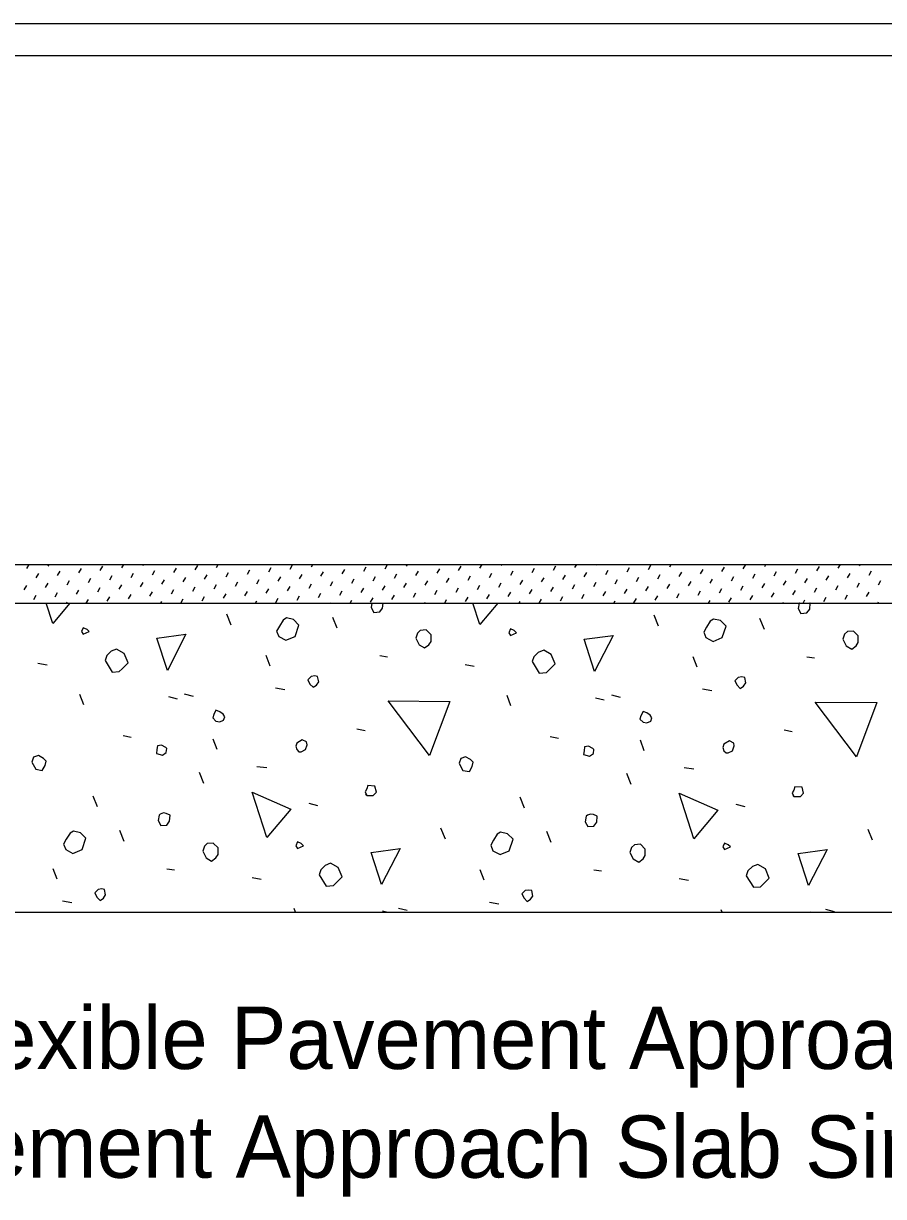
# Model space of a CAD drawing. Extents: x 130649.2 to 130733.9, y 88659.3 to 88705.5.
# Drawn here: x 130675.883 to 130678.667, y 88685.836 to 88689.631 of the extents above; entities that cross this region are included whole.
import ezdxf

# ---------------------------------------------------------------- set-up
doc = ezdxf.new("R2010")
doc.units = 0
for name, color, linetype in [('AdhocPoint_dp', 7, 'Continuous'), ('PlotBorder_dp', 7, 'Continuous'), ('TextMisc', 7, 'Continuous')]:
    doc.layers.add(name, color=color, linetype=linetype)

msp = doc.modelspace()

# ---------------------------------------------------------------- linework, layer by layer
at = {"layer": 'AdhocPoint_dp'}
for p, q in [((130673.2282, 88689.6313), (130686.5589, 88689.6313)), ((130673.2282, 88689.5271), (130686.5589, 88689.5271)), ((130673.2282, 88687.8812), (130689.0593, 88687.8812)), ((130673.2282, 88687.7562), (130689.0593, 88687.7562)), ((130673.2282, 88686.7562), (130689.0593, 88686.7562))]:
    msp.add_line(p, q, dxfattribs=at)
at = {"layer": 'TextMisc'}
for p, q in [((130675.8941, 88687.8679), (130675.9019, 88687.8812)), ((130675.9633, 88687.876), (130675.9663, 88687.8812)), ((130675.9938, 88687.8454), (130676.0019, 88687.8594)), ((130676.063, 88687.8535), (130676.0711, 88687.8675)), ((130676.1322, 88687.8616), (130676.1403, 88687.8756)), ((130676.2013, 88687.8697), (130676.208, 88687.8812)), ((130676.2705, 88687.8778), (130676.2724, 88687.8812)), ((130676.301, 88687.8473), (130676.3091, 88687.8613)), ((130676.3702, 88687.8554), (130676.3783, 88687.8694)), ((130676.4393, 88687.8635), (130676.4474, 88687.8775)), ((130676.5085, 88687.8716), (130676.5141, 88687.8812)), ((130676.5777, 88687.8797), (130676.5785, 88687.8812)), ((130676.6082, 88687.8492), (130676.6163, 88687.8632)), ((130676.6774, 88687.8573), (130676.6855, 88687.8713)), ((130676.7465, 88687.8654), (130676.7546, 88687.8794)), ((130676.8157, 88687.8735), (130676.8202, 88687.8812)), ((130676.8462, 88687.843), (130676.8543, 88687.857)), ((130676.9154, 88687.8511), (130676.9235, 88687.8651)), ((130676.9846, 88687.8592), (130676.9927, 88687.8732)), ((130677.0537, 88687.8673), (130677.0618, 88687.8812)), ((130677.1229, 88687.8754), (130677.1263, 88687.8812)), ((130677.1534, 88687.8449), (130677.1615, 88687.8588)), ((130677.2226, 88687.853), (130677.2307, 88687.8669)), ((130677.2917, 88687.8611), (130677.2998, 88687.875)), ((130677.3609, 88687.8692), (130677.3679, 88687.8812)), ((130677.4301, 88687.8773), (130677.4324, 88687.8812)), ((130677.4606, 88687.8467), (130677.4687, 88687.8607)), ((130677.5298, 88687.8548), (130677.5379, 88687.8688)), ((130677.5989, 88687.8629), (130677.607, 88687.8769)), ((130677.6681, 88687.871), (130677.674, 88687.8812)), ((130677.7373, 88687.8791), (130677.7385, 88687.8812)), ((130677.7678, 88687.8486), (130677.7759, 88687.8626)), ((130677.837, 88687.8567), (130677.8451, 88687.8707)), ((130677.9061, 88687.8648), (130677.9142, 88687.8788)), ((130677.9753, 88687.8729), (130677.9801, 88687.8812)), ((130678.0058, 88687.8424), (130678.0139, 88687.8564)), ((130678.0444, 88687.881), (130678.0446, 88687.8812)), ((130678.075, 88687.8505), (130678.0831, 88687.8645)), ((130678.1441, 88687.8586), (130678.1522, 88687.8726)), ((130678.2133, 88687.8667), (130678.2214, 88687.8807)), ((130678.2825, 88687.8748), (130678.2862, 88687.8812)), ((130678.313, 88687.8443), (130678.3211, 88687.8583)), ((130678.3822, 88687.8524), (130678.3903, 88687.8664)), ((130678.4513, 88687.8605), (130678.4594, 88687.8745)), ((130678.5205, 88687.8686), (130678.5278, 88687.8812)), ((130678.5897, 88687.8767), (130678.5923, 88687.8812)), ((130678.6202, 88687.8461), (130678.6283, 88687.8601)), ((130675.9247, 88687.8373), (130675.9328, 88687.8513)), ((130675.9552, 88687.8068), (130675.9633, 88687.8208)), ((130676.0244, 88687.8149), (130676.0325, 88687.8289)), ((130676.0935, 88687.823), (130676.1016, 88687.837)), ((130676.1627, 88687.8311), (130676.1708, 88687.8451)), ((130676.2319, 88687.8392), (130676.24, 88687.8532)), ((130676.2624, 88687.8087), (130676.2705, 88687.8227)), ((130676.3316, 88687.8168), (130676.3397, 88687.8308)), ((130676.4007, 88687.8249), (130676.4088, 88687.8389)), ((130676.4699, 88687.833), (130676.478, 88687.847)), ((130676.539, 88687.8411), (130676.5471, 88687.8551)), ((130676.5696, 88687.8106), (130676.5777, 88687.8246)), ((130676.6387, 88687.8187), (130676.6468, 88687.8327)), ((130676.7079, 88687.8268), (130676.716, 88687.8408)), ((130676.7771, 88687.8349), (130676.7852, 88687.8489)), ((130676.8076, 88687.8043), (130676.8157, 88687.8183)), ((130676.8768, 88687.8124), (130676.8849, 88687.8264)), ((130676.9459, 88687.8205), (130676.954, 88687.8345)), ((130677.0151, 88687.8286), (130677.0232, 88687.8426)), ((130677.0843, 88687.8367), (130677.0924, 88687.8507)), ((130677.1148, 88687.8062), (130677.1229, 88687.8202)), ((130677.1839, 88687.8143), (130677.192, 88687.8283)), ((130677.2531, 88687.8224), (130677.2612, 88687.8364)), ((130677.3223, 88687.8305), (130677.3304, 88687.8445)), ((130677.3914, 88687.8386), (130677.3995, 88687.8526)), ((130677.422, 88687.8081), (130677.4301, 88687.8221)), ((130677.4911, 88687.8162), (130677.4992, 88687.8302)), ((130677.5603, 88687.8243), (130677.5684, 88687.8383)), ((130677.6295, 88687.8324), (130677.6376, 88687.8464)), ((130677.6986, 88687.8405), (130677.7067, 88687.8545)), ((130677.7292, 88687.81), (130677.7373, 88687.824)), ((130677.7983, 88687.8181), (130677.8064, 88687.8321)), ((130677.8675, 88687.8262), (130677.8756, 88687.8402)), ((130677.9366, 88687.8343), (130677.9447, 88687.8483)), ((130677.9672, 88687.8037), (130677.9753, 88687.8177)), ((130678.0363, 88687.8119), (130678.0444, 88687.8258)), ((130678.1055, 88687.82), (130678.1136, 88687.8339)), ((130678.1747, 88687.8281), (130678.1828, 88687.8421)), ((130678.2438, 88687.8362), (130678.2519, 88687.8502)), ((130678.2744, 88687.8056), (130678.2825, 88687.8196)), ((130678.3435, 88687.8137), (130678.3516, 88687.8277)), ((130678.4127, 88687.8218), (130678.4208, 88687.8358)), ((130678.4819, 88687.8299), (130678.49, 88687.8439)), ((130678.551, 88687.838), (130678.5591, 88687.852)), ((130678.5815, 88687.8075), (130678.5897, 88687.8215)), ((130678.6507, 88687.8156), (130678.6588, 88687.8296)), ((130675.886, 88687.7987), (130675.8941, 88687.8127)), ((130675.9166, 88687.7682), (130675.9247, 88687.7822)), ((130675.9857, 88687.7763), (130675.9938, 88687.7903)), ((130676.0549, 88687.7844), (130676.063, 88687.7984)), ((130676.1241, 88687.7925), (130676.1322, 88687.8065)), ((130676.1932, 88687.8006), (130676.2013, 88687.8146)), ((130676.2238, 88687.7701), (130676.2319, 88687.784)), ((130676.2929, 88687.7782), (130676.301, 88687.7921)), ((130676.3621, 88687.7863), (130676.3702, 88687.8003)), ((130676.4312, 88687.7944), (130676.4393, 88687.8084)), ((130676.5004, 88687.8025), (130676.5085, 88687.8165)), ((130676.5309, 88687.7719), (130676.539, 88687.7859)), ((130676.6001, 88687.78), (130676.6082, 88687.794)), ((130676.6693, 88687.7881), (130676.6774, 88687.8021)), ((130676.7384, 88687.7962), (130676.7465, 88687.8102)), ((130676.769, 88687.7657), (130676.7771, 88687.7797)), ((130676.8381, 88687.7738), (130676.8462, 88687.7878)), ((130676.9073, 88687.7819), (130676.9154, 88687.7959)), ((130676.9765, 88687.79), (130676.9846, 88687.804)), ((130677.0456, 88687.7981), (130677.0537, 88687.8121)), ((130677.0761, 88687.7676), (130677.0843, 88687.7816)), ((130677.1453, 88687.7757), (130677.1534, 88687.7897)), ((130677.2145, 88687.7838), (130677.2226, 88687.7978)), ((130677.2836, 88687.7919), (130677.2917, 88687.8059)), ((130677.3528, 88687.8), (130677.3609, 88687.814)), ((130677.3833, 88687.7695), (130677.3914, 88687.7835)), ((130677.4525, 88687.7776), (130677.4606, 88687.7916)), ((130677.5217, 88687.7857), (130677.5298, 88687.7997)), ((130677.5908, 88687.7938), (130677.5989, 88687.8078)), ((130677.66, 88687.8019), (130677.6681, 88687.8159)), ((130677.6905, 88687.7713), (130677.6986, 88687.7853)), ((130677.7597, 88687.7794), (130677.7678, 88687.7934)), ((130677.8288, 88687.7875), (130677.837, 88687.8015)), ((130677.898, 88687.7956), (130677.9061, 88687.8096)), ((130677.9977, 88687.7732), (130678.0058, 88687.7872)), ((130678.0669, 88687.7813), (130678.075, 88687.7953)), ((130678.136, 88687.7894), (130678.1441, 88687.8034)), ((130678.2052, 88687.7975), (130678.2133, 88687.8115)), ((130678.2357, 88687.767), (130678.2438, 88687.781)), ((130678.3049, 88687.7751), (130678.313, 88687.7891)), ((130678.3741, 88687.7832), (130678.3822, 88687.7972)), ((130678.4432, 88687.7913), (130678.4513, 88687.8053)), ((130678.5124, 88687.7994), (130678.5205, 88687.8134)), ((130678.5429, 88687.7689), (130678.551, 88687.7829)), ((130678.6121, 88687.777), (130678.6202, 88687.791)), ((130676.0223, 88687.7562), (130676.0244, 88687.7597)), ((130676.0868, 88687.7562), (130676.0935, 88687.7678)), ((130676.1546, 88687.7619), (130676.1627, 88687.7759)), ((130676.3284, 88687.7562), (130676.3316, 88687.7616)), ((130676.3929, 88687.7562), (130676.4007, 88687.7697)), ((130676.4618, 88687.7638), (130676.4699, 88687.7778)), ((130676.6345, 88687.7562), (130676.6387, 88687.7635)), ((130676.6998, 88687.7576), (130676.7079, 88687.7716)), ((130676.8761, 88687.7562), (130676.8768, 88687.7573)), ((130676.9406, 88687.7562), (130676.9459, 88687.7654)), ((130677.007, 88687.7595), (130677.0151, 88687.7735)), ((130677.1822, 88687.7562), (130677.1839, 88687.7592)), ((130677.2467, 88687.7562), (130677.2531, 88687.7673)), ((130677.3142, 88687.7614), (130677.3223, 88687.7754)), ((130677.4883, 88687.7562), (130677.4911, 88687.761)), ((130677.5528, 88687.7562), (130677.5603, 88687.7691)), ((130677.6214, 88687.7632), (130677.6295, 88687.7772)), ((130677.7944, 88687.7562), (130677.7983, 88687.7629)), ((130677.8594, 88687.757), (130677.8675, 88687.771)), ((130677.9285, 88687.7651), (130677.9366, 88687.7791)), ((130678.0361, 88687.7562), (130678.0363, 88687.7567)), ((130678.1005, 88687.7562), (130678.1055, 88687.7648)), ((130678.1666, 88687.7589), (130678.1747, 88687.7729)), ((130678.3422, 88687.7562), (130678.3435, 88687.7586)), ((130678.4066, 88687.7562), (130678.4127, 88687.7667)), ((130678.4738, 88687.7608), (130678.4819, 88687.7748)), ((130678.6483, 88687.7562), (130678.6507, 88687.7604)), ((130676.556, 88687.6851), (130676.5419, 88687.7205)), ((130676.899, 88687.6745), (130676.8848, 88687.7098)), ((130677.9384, 88687.6816), (130677.9243, 88687.7169)), ((130678.2814, 88687.671), (130678.2672, 88687.7063)), ((130675.9302, 88687.5614), (130675.9603, 88687.5561)), ((130676.6815, 88687.5525), (130676.6692, 88687.5861)), ((130677.0368, 88687.5861), (130677.0616, 88687.5826)), ((130677.3126, 88687.5578), (130677.3427, 88687.5525)), ((130678.0639, 88687.549), (130678.0515, 88687.5826)), ((130678.4192, 88687.5826), (130678.444, 88687.579)), ((130676.6992, 88687.4818), (130676.7293, 88687.4765)), ((130678.0816, 88687.4783), (130678.1116, 88687.473)), ((130676.0787, 88687.427), (130676.0663, 88687.4606)), ((130676.3527, 88687.4535), (130676.381, 88687.4464)), ((130676.404, 88687.4624), (130676.4323, 88687.4553)), ((130677.4611, 88687.4235), (130677.4487, 88687.4571)), ((130677.7351, 88687.45), (130677.7634, 88687.4429)), ((130677.7864, 88687.4588), (130677.8147, 88687.4518)), ((130676.206, 88687.328), (130676.2325, 88687.3227)), ((130676.9626, 88687.3492), (130676.9891, 88687.3439)), ((130677.5884, 88687.3245), (130677.6149, 88687.3192)), ((130678.345, 88687.3457), (130678.3715, 88687.3404)), ((130676.5101, 88687.282), (130676.4977, 88687.3156)), ((130677.8924, 88687.2785), (130677.8801, 88687.3121)), ((130676.6391, 88687.2272), (130676.6709, 88687.2237)), ((130678.0215, 88687.2237), (130678.0533, 88687.2202)), ((130676.4676, 88687.1724), (130676.4535, 88687.2078)), ((130677.85, 88687.1689), (130677.8359, 88687.2043)), ((130676.1229, 88687.0964), (130676.1088, 88687.1318)), ((130676.807, 88687.1088), (130676.8353, 88687.1017)), ((130677.5053, 88687.0929), (130677.4912, 88687.1283)), ((130678.1894, 88687.1053), (130678.2177, 88687.0982)), ((130677.249, 88686.9921), (130677.2348, 88687.0275)), ((130678.6314, 88686.9886), (130678.6172, 88687.024)), ((130676.2095, 88686.9851), (130676.1954, 88687.0204)), ((130677.5919, 88686.9815), (130677.5778, 88687.0169)), ((130675.9921, 88686.8631), (130675.9797, 88686.8967)), ((130676.3474, 88686.8967), (130676.3722, 88686.8931)), ((130677.3745, 88686.8596), (130677.3621, 88686.8931)), ((130677.7298, 88686.8931), (130677.7546, 88686.8896)), ((130676.6232, 88686.8684), (130676.6532, 88686.8631)), ((130678.0056, 88686.8649), (130678.0356, 88686.8596)), ((130676.0098, 88686.7924), (130676.0398, 88686.7871)), ((130676.7635, 88686.7562), (130676.7593, 88686.7676)), ((130677.0457, 88686.7606), (130677.0631, 88686.7562)), ((130677.097, 88686.7694), (130677.1252, 88686.7623)), ((130677.3922, 88686.7888), (130677.4222, 88686.7835)), ((130678.1446, 88686.7562), (130678.1417, 88686.7641)), ((130678.4281, 88686.757), (130678.4313, 88686.7562)), ((130678.4793, 88686.7659), (130678.5076, 88686.7588))]:
    msp.add_line(p, q, dxfattribs=at)
for points in [[(130675.978, 88687.6904), (130675.9565, 88687.7562)], [(130676.0336, 88687.7562), (130675.978, 88687.6904)], [(130677.0086, 88687.7417), (130677.0174, 88687.7258), (130677.0368, 88687.7275), (130677.0457, 88687.7399), (130677.0472, 88687.7562)], [(130677.0115, 88687.7562), (130677.0086, 88687.7417)], [(130677.3603, 88687.6869), (130677.3378, 88687.7562)], [(130677.419, 88687.7562), (130677.3603, 88687.6869)], [(130678.391, 88687.7381), (130678.3998, 88687.7222), (130678.4192, 88687.724), (130678.4281, 88687.7364), (130678.4298, 88687.7558), (130678.4289, 88687.7562)], [(130678.3949, 88687.7562), (130678.3945, 88687.7558), (130678.391, 88687.7381)], [(130676.7098, 88687.648), (130676.7328, 88687.6356), (130676.7628, 88687.648), (130676.7752, 88687.6851), (130676.7575, 88687.7028), (130676.7346, 88687.7081), (130676.724, 88687.701), (130676.7116, 88687.6816), (130676.7027, 88687.6657), (130676.7098, 88687.648)], [(130678.0922, 88687.6444), (130678.1152, 88687.6321), (130678.1452, 88687.6444), (130678.1576, 88687.6816), (130678.1399, 88687.6992), (130678.117, 88687.7045), (130678.1063, 88687.6975), (130678.094, 88687.678), (130678.0851, 88687.6621), (130678.0922, 88687.6444)], [(130676.0769, 88687.655), (130676.0964, 88687.6639), (130676.0893, 88687.671), (130676.0769, 88687.6763), (130676.0716, 88687.6639), (130676.0769, 88687.655)], [(130677.1535, 88687.6427), (130677.1641, 88687.6215), (130677.1818, 88687.6109), (130677.1959, 88687.6215), (130677.203, 88687.6321), (130677.203, 88687.6533), (130677.1871, 88687.6692), (130677.1677, 88687.6674), (130677.1588, 88687.6586), (130677.1535, 88687.6427)], [(130677.4593, 88687.6515), (130677.4788, 88687.6603), (130677.4717, 88687.6674), (130677.4593, 88687.6727), (130677.454, 88687.6603), (130677.4593, 88687.6515)], [(130676.3492, 88687.5384), (130676.3156, 88687.6427), (130676.4093, 88687.655), (130676.3492, 88687.5384)], [(130677.7316, 88687.5348), (130677.698, 88687.6391), (130677.7917, 88687.6515), (130677.7316, 88687.5348)], [(130678.5359, 88687.6391), (130678.5465, 88687.6179), (130678.5642, 88687.6073), (130678.5783, 88687.6179), (130678.5854, 88687.6285), (130678.5854, 88687.6497), (130678.5695, 88687.6657), (130678.5501, 88687.6639), (130678.5412, 88687.655), (130678.5359, 88687.6391)], [(130676.1477, 88687.5702), (130676.1706, 88687.5331), (130676.1936, 88687.5348), (130676.2025, 88687.5437), (130676.2219, 88687.5631), (130676.2095, 88687.5932), (130676.1848, 88687.6073), (130676.1671, 88687.6002), (130676.153, 88687.5861), (130676.1477, 88687.5702)], [(130677.5301, 88687.5667), (130677.553, 88687.5295), (130677.576, 88687.5313), (130677.5849, 88687.5401), (130677.6043, 88687.5596), (130677.5919, 88687.5896), (130677.5672, 88687.6038), (130677.5495, 88687.5967), (130677.5354, 88687.5826), (130677.5301, 88687.5667)], [(130676.8106, 88687.4942), (130676.8212, 88687.4836), (130676.8318, 88687.4906), (130676.8389, 88687.5012), (130676.8353, 88687.5189), (130676.8265, 88687.5207), (130676.8141, 88687.5189), (130676.8035, 88687.5083), (130676.8106, 88687.4942)], [(130678.193, 88687.4906), (130678.2036, 88687.48), (130678.2142, 88687.4871), (130678.2213, 88687.4977), (130678.2177, 88687.5154), (130678.2089, 88687.5172), (130678.1965, 88687.5154), (130678.1859, 88687.5048), (130678.193, 88687.4906)], [(130677.1977, 88687.2626), (130677.0634, 88687.4394), (130677.2631, 88687.4376), (130677.1977, 88687.2626)], [(130676.5065, 88687.374), (130676.5189, 88687.3722), (130676.5313, 88687.3775), (130676.5348, 88687.3881), (130676.5295, 88687.397), (130676.5189, 88687.404), (130676.5065, 88687.4093), (130676.4994, 88687.3952), (130676.4959, 88687.3846), (130676.5065, 88687.374)], [(130677.8889, 88687.3704), (130677.9013, 88687.3687), (130677.9137, 88687.374), (130677.9172, 88687.3846), (130677.9119, 88687.3934), (130677.9013, 88687.4005), (130677.8889, 88687.4058), (130677.8818, 88687.3916), (130677.8783, 88687.381), (130677.8889, 88687.3704)], [(130678.5801, 88687.2591), (130678.4458, 88687.4358), (130678.6455, 88687.4341), (130678.5801, 88687.2591)], [(130676.3138, 88687.2697), (130676.3333, 88687.2644), (130676.3457, 88687.2732), (130676.3474, 88687.2856), (130676.3439, 88687.2891), (130676.3297, 88687.2962), (130676.3174, 88687.2944), (130676.3156, 88687.282), (130676.3138, 88687.2697)], [(130676.7752, 88687.275), (130676.7823, 88687.275), (130676.7964, 88687.282), (130676.8017, 88687.298), (130676.8, 88687.3068), (130676.7858, 88687.3139), (130676.7681, 88687.3033), (130676.7646, 88687.2927), (130676.7681, 88687.282), (130676.7752, 88687.275)], [(130677.6962, 88687.2661), (130677.7157, 88687.2608), (130677.728, 88687.2697), (130677.7298, 88687.282), (130677.7263, 88687.2856), (130677.7121, 88687.2927), (130677.6998, 88687.2909), (130677.698, 88687.2785), (130677.6962, 88687.2661)], [(130678.1576, 88687.2714), (130678.1647, 88687.2714), (130678.1788, 88687.2785), (130678.1841, 88687.2944), (130678.1824, 88687.3033), (130678.1682, 88687.3103), (130678.1505, 88687.2997), (130678.147, 88687.2891), (130678.1505, 88687.2785), (130678.1576, 88687.2714)], [(130675.9143, 88687.2343), (130675.9232, 88687.2184), (130675.9444, 88687.2149), (130675.9532, 88687.2308), (130675.9567, 88687.2449), (130675.9479, 88687.2538), (130675.932, 88687.2626), (130675.9161, 88687.2573), (130675.9108, 88687.2414), (130675.9143, 88687.2343)], [(130677.2967, 88687.2308), (130677.3055, 88687.2149), (130677.3268, 88687.2113), (130677.3356, 88687.2272), (130677.3391, 88687.2414), (130677.3303, 88687.2502), (130677.3144, 88687.2591), (130677.2985, 88687.2538), (130677.2932, 88687.2379), (130677.2967, 88687.2308)], [(130676.6709, 88686.9974), (130676.6232, 88687.1442), (130676.7487, 88687.0894), (130676.6709, 88686.9974)], [(130676.9944, 88687.1336), (130677.0156, 88687.1336), (130677.0262, 88687.1442), (130677.0209, 88687.1636), (130676.998, 88687.1654), (130676.9944, 88687.1548), (130676.9891, 88687.1459), (130676.9944, 88687.1336), (130676.9909, 88687.1371)], [(130678.0533, 88686.9939), (130678.0056, 88687.1406), (130678.1311, 88687.0858), (130678.0533, 88686.9939)], [(130678.3768, 88687.13), (130678.398, 88687.13), (130678.4086, 88687.1406), (130678.4033, 88687.1601), (130678.3804, 88687.1618), (130678.3768, 88687.1512), (130678.3715, 88687.1424), (130678.3768, 88687.13), (130678.3733, 88687.1336)], [(130676.3191, 88687.0522), (130676.328, 88687.0363), (130676.3474, 88687.0381), (130676.3563, 88687.0505), (130676.358, 88687.0699), (130676.3457, 88687.0752), (130676.3368, 88687.077), (130676.3262, 88687.0735), (130676.3227, 88687.0699), (130676.3191, 88687.0522)], [(130677.7015, 88687.0487), (130677.7104, 88687.0328), (130677.7298, 88687.0346), (130677.7387, 88687.0469), (130677.7404, 88687.0664), (130677.728, 88687.0717), (130677.7192, 88687.0735), (130677.7086, 88687.0699), (130677.7051, 88687.0664), (130677.7015, 88687.0487)], [(130676.0204, 88686.9585), (130676.0434, 88686.9462), (130676.0734, 88686.9585), (130676.0858, 88686.9957), (130676.0681, 88687.0133), (130676.0451, 88687.0186), (130676.0345, 88687.0116), (130676.0221, 88686.9921), (130676.0133, 88686.9762), (130676.0204, 88686.9585)], [(130676.7699, 88686.9621), (130676.7894, 88686.9709), (130676.7823, 88686.978), (130676.7699, 88686.9833), (130676.7646, 88686.9709), (130676.7699, 88686.9621)], [(130677.4028, 88686.955), (130677.4258, 88686.9426), (130677.4558, 88686.955), (130677.4682, 88686.9921), (130677.4505, 88687.0098), (130677.4275, 88687.0151), (130677.4169, 88687.008), (130677.4045, 88686.9886), (130677.3957, 88686.9727), (130677.4028, 88686.955)], [(130676.4641, 88686.9532), (130676.4747, 88686.932), (130676.4924, 88686.9214), (130676.5065, 88686.932), (130676.5136, 88686.9426), (130676.5136, 88686.9638), (130676.4977, 88686.9798), (130676.4782, 88686.978), (130676.4694, 88686.9692), (130676.4641, 88686.9532)], [(130677.0422, 88686.8454), (130677.0086, 88686.9497), (130677.1023, 88686.9621), (130677.0422, 88686.8454)], [(130677.8465, 88686.9497), (130677.8571, 88686.9285), (130677.8748, 88686.9179), (130677.8889, 88686.9285), (130677.896, 88686.9391), (130677.896, 88686.9603), (130677.8801, 88686.9762), (130677.8606, 88686.9745), (130677.8518, 88686.9656), (130677.8465, 88686.9497)], [(130678.1523, 88686.9585), (130678.1718, 88686.9674), (130678.1647, 88686.9745), (130678.1523, 88686.9798), (130678.147, 88686.9674), (130678.1523, 88686.9585)], [(130678.4245, 88686.8419), (130678.391, 88686.9462), (130678.4846, 88686.9585), (130678.4245, 88686.8419)], [(130676.8406, 88686.8772), (130676.8636, 88686.8401), (130676.8866, 88686.8419), (130676.8954, 88686.8507), (130676.9149, 88686.8702), (130676.9025, 88686.9002), (130676.8777, 88686.9144), (130676.8601, 88686.9073), (130676.8459, 88686.8931), (130676.8406, 88686.8772)], [(130678.223, 88686.8737), (130678.246, 88686.8366), (130678.269, 88686.8383), (130678.2778, 88686.8472), (130678.2973, 88686.8666), (130678.2849, 88686.8967), (130678.2601, 88686.9108), (130678.2425, 88686.9037), (130678.2283, 88686.8896), (130678.223, 88686.8737)], [(130676.1211, 88686.8047), (130676.1318, 88686.7941), (130676.1424, 88686.8012), (130676.1494, 88686.8118), (130676.1459, 88686.8295), (130676.1371, 88686.8313), (130676.1247, 88686.8295), (130676.1141, 88686.8189), (130676.1211, 88686.8047)], [(130677.5035, 88686.8012), (130677.5141, 88686.7906), (130677.5248, 88686.7977), (130677.5318, 88686.8083), (130677.5283, 88686.826), (130677.5194, 88686.8277), (130677.5071, 88686.826), (130677.4965, 88686.8154), (130677.5035, 88686.8012)]]:
    msp.add_lwpolyline(points, dxfattribs=at)

# ---------------------------------------------------------------- texts
at = {"layer": 'PlotBorder_dp'}
for s, p in [('Approach Slab (Flexible Pavement Approach Slab ', (130673.6177, 88686.2489)), ('Shown, Rigid Pavement Approach Slab Similar)', (130673.6177, 88685.8969))]:
    msp.add_text(s, height=0.2016, dxfattribs=at).set_placement(p)

doc.saveas('drawing.dxf')
